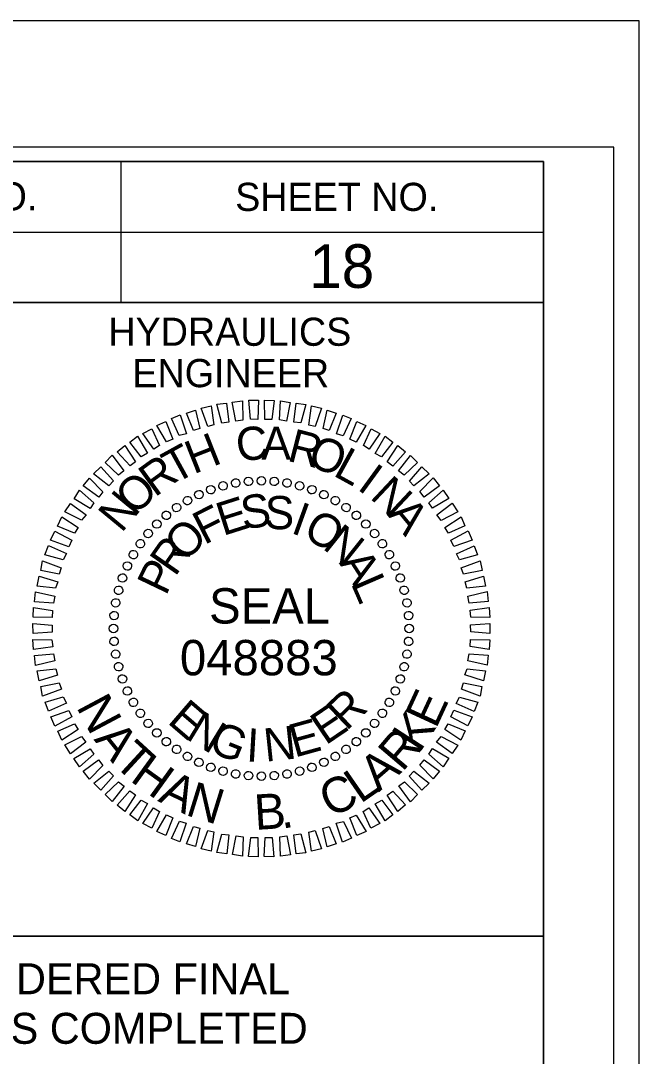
# Model space of a CAD drawing. Extents: x 1648435 to 1651603, y 802691 to 845762.
# Drawn here: x 1650436.5 to 1650546.3, y 803607.1 to 803791 of the extents above; entities that cross this region are included whole.
import ezdxf

# ---------------------------------------------------------------- set-up
doc = ezdxf.new("R2010")
doc.units = 0
for name, color, linetype in [('Default', 7, 'Continuous'), ('Old_Level_2', 7, 'Continuous'), ('Sheet Cutting Line CELL', 7, 'Continuous'), ('Sheet Data Field CELL', 7, 'Continuous'), ('Sheet Plot Border Inside CELL', 7, 'Continuous'), ('Sheet Plot Border Outside CELL', 7, 'Continuous'), ('Sheet Profile CELL', 7, 'Continuous'), ('Sheet Profile Grid Major CELL', 7, 'Continuous'), ('Sheet Sticker Exception Certification CELL', 7, 'Continuous')]:
    doc.layers.add(name, color=color, linetype=linetype)

msp = doc.modelspace()

# ---------------------------------------------------------------- linework, layer by layer
at = {"layer": 'Old_Level_2'}
for p, q in [((1650476.94, 803709.25), (1650476.94, 803709.25)), ((1650479.24, 803709.34), (1650479.24, 803709.34)), ((1650481.55, 803709.22), (1650481.55, 803709.22)), ((1650470.22, 803707.77), (1650470.22, 803707.77)), ((1650472.41, 803708.44), (1650472.41, 803708.44)), ((1650474.7, 803708.89), (1650474.7, 803708.89)), ((1650483.8, 803708.9), (1650483.8, 803708.9)), ((1650486.01, 803708.46), (1650486.01, 803708.46)), ((1650488.21, 803707.77), (1650488.21, 803707.77)), ((1650466.13, 803705.82), (1650466.13, 803705.82)), ((1650468.15, 803706.9), (1650468.15, 803706.9)), ((1650490.32, 803706.87), (1650490.32, 803706.87)), ((1650492.38, 803705.86), (1650492.38, 803705.86)), ((1650464.16, 803704.58), (1650464.16, 803704.58)), ((1650494.28, 803704.58), (1650494.28, 803704.58)), ((1650460.66, 803701.64), (1650460.66, 803701.64)), ((1650462.35, 803703.24), (1650462.35, 803703.24)), ((1650496.14, 803703.2), (1650496.14, 803703.2)), ((1650497.79, 803701.66), (1650497.79, 803701.66)), ((1650459.12, 803699.99), (1650459.12, 803699.99)), ((1650499.38, 803699.96), (1650499.38, 803699.96)), ((1650457.74, 803698.14), (1650457.74, 803698.14)), ((1650500.72, 803698.16), (1650500.72, 803698.16)), ((1650456.46, 803696.23), (1650456.46, 803696.23)), ((1650501.96, 803696.19), (1650501.96, 803696.19)), ((1650455.45, 803694.18), (1650455.45, 803694.18)), ((1650503.04, 803694.17), (1650503.04, 803694.17)), ((1650454.55, 803692.07), (1650454.55, 803692.07)), ((1650503.91, 803692.09), (1650503.91, 803692.09)), ((1650453.85, 803689.86), (1650453.85, 803689.86)), ((1650504.58, 803689.91), (1650504.58, 803689.91)), ((1650453.42, 803687.66), (1650453.42, 803687.66)), ((1650505.04, 803687.62), (1650505.04, 803687.62)), ((1650453.1, 803685.4), (1650453.1, 803685.4)), ((1650505.39, 803685.37), (1650505.39, 803685.37)), ((1650452.98, 803683.1), (1650452.98, 803683.1)), ((1650479.23, 803683.09), (1650479.23, 803683.09)), ((1650505.48, 803683.07), (1650505.48, 803683.07)), ((1650453.07, 803680.8), (1650453.07, 803680.8)), ((1650505.37, 803680.77), (1650505.37, 803680.77)), ((1650453.42, 803678.56), (1650453.42, 803678.56)), ((1650505.04, 803678.52), (1650505.04, 803678.52)), ((1650453.88, 803676.26), (1650453.88, 803676.26)), ((1650504.61, 803676.31), (1650504.61, 803676.31)), ((1650454.55, 803674.08), (1650454.55, 803674.08)), ((1650503.92, 803674.1), (1650503.92, 803674.1)), ((1650455.42, 803672), (1650455.42, 803672)), ((1650503.01, 803672), (1650503.01, 803672)), ((1650456.5, 803669.98), (1650456.5, 803669.98)), ((1650502, 803669.94), (1650502, 803669.94)), ((1650457.74, 803668.02), (1650457.74, 803668.02)), ((1650500.73, 803668.03), (1650500.73, 803668.03)), ((1650459.08, 803666.21), (1650459.08, 803666.21)), ((1650499.35, 803666.18), (1650499.35, 803666.18)), ((1650460.68, 803664.51), (1650460.68, 803664.51)), ((1650497.81, 803664.53), (1650497.81, 803664.53)), ((1650462.32, 803662.97), (1650462.32, 803662.97)), ((1650464.18, 803661.59), (1650464.18, 803661.59)), ((1650494.3, 803661.59), (1650494.3, 803661.59)), ((1650496.11, 803662.93), (1650496.11, 803662.93)), ((1650466.08, 803660.32), (1650466.08, 803660.32)), ((1650468.14, 803659.31), (1650468.14, 803659.31)), ((1650492.34, 803660.36), (1650492.34, 803660.36)), ((1650470.25, 803658.4), (1650470.25, 803658.4)), ((1650472.46, 803657.71), (1650472.46, 803657.71)), ((1650486.05, 803657.74), (1650486.05, 803657.74)), ((1650488.24, 803658.4), (1650488.24, 803658.4)), ((1650490.32, 803659.28), (1650490.32, 803659.28)), ((1650474.66, 803657.28), (1650474.66, 803657.28)), ((1650476.92, 803656.95), (1650476.92, 803656.95)), ((1650479.22, 803656.83), (1650479.22, 803656.83)), ((1650481.52, 803656.93), (1650481.52, 803656.93)), ((1650483.76, 803657.28), (1650483.76, 803657.28))]:
    msp.add_line(p, q, dxfattribs=at)
for points in [[(1650467.22, 803718.23), (1650465.96, 803721.34), (1650467.57, 803721.84), (1650468.31, 803718.61)], [(1650469.71, 803718.95), (1650468.56, 803722.23), (1650470.33, 803722.62), (1650470.81, 803719.23)], [(1650472.21, 803719.57), (1650471.32, 803722.9), (1650473.04, 803723.09), (1650473.47, 803719.75)], [(1650474.72, 803719.93), (1650474.08, 803723.26), (1650475.86, 803723.5), (1650475.97, 803720.11)], [(1650477.33, 803720.24), (1650477.01, 803723.63), (1650478.73, 803723.61), (1650478.58, 803720.21)], [(1650479.84, 803720.23), (1650479.78, 803723.63), (1650481.5, 803723.6), (1650481.09, 803720.2)], [(1650482.45, 803720.12), (1650482.6, 803723.52), (1650484.34, 803723.23), (1650483.71, 803719.93)], [(1650484.97, 803719.74), (1650485.38, 803723.1), (1650487.11, 803722.86), (1650486.23, 803719.61)], [(1650487.65, 803719.21), (1650488.11, 803722.62), (1650489.9, 803722.23), (1650488.75, 803718.97)], [(1650464.67, 803717.35), (1650463.26, 803720.36), (1650464.82, 803721.01), (1650465.97, 803717.68)], [(1650490.17, 803718.58), (1650490.9, 803721.83), (1650492.53, 803721.34), (1650491.27, 803718.23)], [(1650492.54, 803717.68), (1650493.68, 803720.99), (1650495.16, 803720.39), (1650493.75, 803717.33)], [(1650460.16, 803714.92), (1650458.18, 803717.71), (1650459.79, 803718.57), (1650461.15, 803715.56)], [(1650462.39, 803716.21), (1650460.66, 803719.11), (1650462.27, 803719.87), (1650463.53, 803716.7)], [(1650494.91, 803716.72), (1650496.16, 803719.83), (1650497.79, 803719.13), (1650496.07, 803716.17)], [(1650497.33, 803715.56), (1650498.69, 803718.57), (1650500.28, 803717.71), (1650498.34, 803714.95)], [(1650457.89, 803713.57), (1650455.9, 803716.2), (1650457.25, 803717.22), (1650459.02, 803714.22)], [(1650499.4, 803714.19), (1650501.17, 803717.25), (1650502.55, 803716.18), (1650500.56, 803713.58)], [(1650455.93, 803711.97), (1650453.63, 803714.44), (1650455.03, 803715.56), (1650456.91, 803712.66)], [(1650501.57, 803712.66), (1650503.45, 803715.57), (1650504.83, 803714.44), (1650502.57, 803711.94)], [(1650453.86, 803710.31), (1650451.52, 803712.57), (1650452.76, 803713.85), (1650454.84, 803711.06)], [(1650503.58, 803711.07), (1650505.68, 803713.83), (1650506.96, 803712.59), (1650504.59, 803710.3)], [(1650452.17, 803708.45), (1650449.47, 803710.55), (1650450.75, 803711.77), (1650452.99, 803709.3)], [(1650505.5, 803709.27), (1650507.7, 803711.77), (1650508.98, 803710.54), (1650506.3, 803708.45)], [(1650450.37, 803706.43), (1650447.62, 803708.42), (1650448.75, 803709.8), (1650451.09, 803707.38)], [(1650507.36, 803707.42), (1650509.72, 803709.82), (1650510.85, 803708.43), (1650508.11, 803706.39)], [(1650448.84, 803704.42), (1650445.99, 803706.14), (1650446.95, 803707.68), (1650449.5, 803705.42)], [(1650508.96, 803705.41), (1650511.49, 803707.65), (1650512.51, 803706.15), (1650509.61, 803704.43)], [(1650447.31, 803702.3), (1650444.35, 803703.81), (1650445.37, 803705.3), (1650448.13, 803703.25)], [(1650510.36, 803703.29), (1650513.1, 803705.33), (1650514.12, 803703.78), (1650511.11, 803702.26)], [(1650446.09, 803700.03), (1650443.09, 803701.28), (1650443.85, 803702.92), (1650446.7, 803701.03)], [(1650511.76, 803701.02), (1650514.66, 803702.9), (1650515.36, 803701.29), (1650512.41, 803700.03)], [(1650445.09, 803697.6), (1650441.83, 803698.75), (1650442.58, 803700.38), (1650445.59, 803698.76)], [(1650512.85, 803698.79), (1650515.9, 803700.41), (1650516.61, 803698.75), (1650513.39, 803697.65)], [(1650444.08, 803695.29), (1650440.83, 803696.17), (1650441.48, 803697.8), (1650444.64, 803696.39)], [(1650513.83, 803696.35), (1650516.99, 803697.76), (1650517.6, 803696.15), (1650514.37, 803695.26)], [(1650443.34, 803692.76), (1650440.09, 803693.39), (1650440.43, 803695.12), (1650443.74, 803693.87)], [(1650514.71, 803693.85), (1650518.03, 803695.11), (1650518.38, 803693.39), (1650515.09, 803692.76)], [(1650442.71, 803690.24), (1650439.46, 803690.6), (1650439.79, 803692.39), (1650443.11, 803691.35)], [(1650515.38, 803691.35), (1650518.66, 803692.4), (1650519, 803690.63), (1650515.71, 803690.26)], [(1650442.34, 803687.57), (1650438.99, 803687.82), (1650439.16, 803689.6), (1650442.58, 803688.83)], [(1650515.89, 803688.85), (1650519.28, 803689.64), (1650519.47, 803687.87), (1650516.13, 803687.6)], [(1650442.12, 803685.05), (1650438.72, 803685.1), (1650438.79, 803686.83), (1650442.2, 803686.31)], [(1650516.25, 803686.35), (1650519.64, 803686.82), (1650519.78, 803685.05), (1650516.38, 803685.09)], [(1650442.11, 803682.44), (1650438.72, 803682.22), (1650438.69, 803684), (1650442.09, 803683.69)], [(1650516.35, 803683.73), (1650519.75, 803683.95), (1650519.78, 803682.17), (1650516.37, 803682.48)], [(1650442.21, 803679.83), (1650438.82, 803679.35), (1650438.68, 803681.12), (1650442.08, 803681.08)], [(1650516.34, 803681.12), (1650519.74, 803681.07), (1650519.67, 803679.35), (1650516.26, 803679.86)], [(1650442.57, 803677.32), (1650439.18, 803676.53), (1650438.99, 803678.3), (1650442.34, 803678.57)], [(1650516.13, 803678.61), (1650519.48, 803678.35), (1650519.3, 803676.57), (1650515.89, 803677.35)], [(1650443.08, 803674.82), (1650439.81, 803673.77), (1650439.46, 803675.54), (1650442.75, 803675.91)], [(1650515.75, 803675.93), (1650519, 803675.57), (1650518.67, 803673.79), (1650515.36, 803674.83)], [(1650443.75, 803672.32), (1650440.43, 803671.06), (1650440.08, 803672.78), (1650443.37, 803673.41)], [(1650515.12, 803673.41), (1650518.37, 803672.79), (1650518.04, 803671.06), (1650514.72, 803672.31)], [(1650444.63, 803669.83), (1650441.47, 803668.41), (1650440.86, 803670.02), (1650444.09, 803670.92)], [(1650514.38, 803670.89), (1650517.64, 803670), (1650516.98, 803668.37), (1650513.82, 803669.78)], [(1650445.62, 803667.39), (1650442.56, 803665.76), (1650441.85, 803667.42), (1650445.07, 803668.53)], [(1650513.37, 803668.57), (1650516.64, 803667.42), (1650515.88, 803665.79), (1650512.87, 803667.41)], [(1650446.7, 803665.16), (1650443.81, 803663.28), (1650443.1, 803664.88), (1650446.06, 803666.14)], [(1650512.37, 803666.15), (1650515.37, 803664.89), (1650514.62, 803663.26), (1650511.76, 803665.14)], [(1650448.1, 803662.88), (1650445.37, 803660.84), (1650444.34, 803662.4), (1650447.35, 803663.91)], [(1650511.15, 803663.88), (1650514.11, 803662.36), (1650513.09, 803660.88), (1650510.33, 803662.92)], [(1650449.5, 803660.76), (1650446.97, 803658.52), (1650445.96, 803660.02), (1650448.85, 803661.74)], [(1650509.62, 803661.76), (1650512.48, 803660.03), (1650511.51, 803658.5), (1650508.96, 803660.75)], [(1650451.1, 803658.75), (1650448.74, 803656.35), (1650447.62, 803657.75), (1650450.35, 803659.78)], [(1650508.09, 803659.74), (1650510.84, 803657.75), (1650509.72, 803656.37), (1650507.37, 803658.79)], [(1650452.97, 803656.9), (1650450.76, 803654.4), (1650449.48, 803655.63), (1650452.17, 803657.72)], [(1650506.29, 803657.72), (1650509, 803655.63), (1650507.71, 803654.4), (1650505.47, 803656.87)], [(1650454.88, 803655.1), (1650452.78, 803652.35), (1650451.51, 803653.58), (1650453.87, 803655.87)], [(1650504.6, 803655.86), (1650506.94, 803653.6), (1650505.71, 803652.33), (1650503.62, 803655.12)], [(1650456.89, 803653.52), (1650455.01, 803650.61), (1650453.63, 803651.73), (1650455.89, 803654.23)], [(1650502.54, 803654.21), (1650504.83, 803651.74), (1650503.44, 803650.61), (1650501.56, 803653.51)], [(1650459.06, 803651.98), (1650457.29, 803648.92), (1650455.91, 803649.99), (1650457.9, 803652.59)], [(1650500.58, 803652.6), (1650502.56, 803649.97), (1650501.22, 803648.95), (1650499.44, 803651.96)], [(1650461.13, 803650.61), (1650459.77, 803647.6), (1650458.18, 803648.46), (1650460.12, 803651.22)], [(1650498.3, 803651.26), (1650500.28, 803648.47), (1650498.68, 803647.6), (1650497.32, 803650.61)], [(1650463.55, 803649.45), (1650462.3, 803646.34), (1650460.67, 803647.04), (1650462.39, 803650)], [(1650465.92, 803648.5), (1650464.78, 803645.18), (1650463.3, 803645.78), (1650464.72, 803648.84)], [(1650493.79, 803648.82), (1650495.2, 803645.82), (1650493.65, 803645.16), (1650492.49, 803648.49)], [(1650496.07, 803649.96), (1650497.8, 803647.06), (1650496.19, 803646.3), (1650494.93, 803649.47)], [(1650468.29, 803647.6), (1650467.57, 803644.34), (1650465.94, 803644.83), (1650467.19, 803647.94)], [(1650470.81, 803646.96), (1650470.35, 803643.55), (1650468.57, 803643.94), (1650469.71, 803647.2)], [(1650473.49, 803646.43), (1650473.08, 803643.08), (1650471.35, 803643.31), (1650472.23, 803646.57)], [(1650486.25, 803646.6), (1650487.14, 803643.27), (1650485.42, 803643.08), (1650485, 803646.42)], [(1650488.75, 803647.22), (1650489.9, 803643.95), (1650488.13, 803643.55), (1650487.65, 803646.94)], [(1650491.25, 803647.94), (1650492.5, 803644.83), (1650490.89, 803644.33), (1650490.15, 803647.56)], [(1650476.01, 803646.06), (1650475.86, 803642.65), (1650474.13, 803642.94), (1650474.75, 803646.24)], [(1650478.62, 803645.95), (1650478.68, 803642.55), (1650476.96, 803642.57), (1650477.37, 803645.98)], [(1650481.13, 803645.94), (1650481.46, 803642.54), (1650479.73, 803642.57), (1650479.88, 803645.97)], [(1650483.74, 803646.24), (1650484.38, 803642.91), (1650482.6, 803642.67), (1650482.49, 803646.07)]]:
    msp.add_lwpolyline(points, close=True, dxfattribs=at)
for centre, major_axis in [((1650472.44, 803708.42), (-0.195, 0.727)), ((1650474.68, 803708.92), (-0.131, 0.742)), ((1650476.95, 803709.21), (-0.066, 0.75)), ((1650479.23, 803709.31), (0, 0.753)), ((1650481.52, 803709.21), (0.066, 0.75)), ((1650483.79, 803708.92), (0.131, 0.742)), ((1650486.02, 803708.42), (0.195, 0.727)), ((1650468.15, 803706.86), (-0.318, 0.682)), ((1650470.26, 803707.73), (-0.258, 0.708)), ((1650488.2, 803707.73), (0.258, 0.708)), ((1650490.32, 803706.86), (0.318, 0.682)), ((1650464.19, 803704.57), (-0.432, 0.617)), ((1650466.12, 803705.8), (-0.376, 0.652)), ((1650492.35, 803705.8), (0.376, 0.652)), ((1650494.27, 803704.57), (0.432, 0.617)), ((1650462.37, 803703.18), (-0.484, 0.577)), ((1650496.09, 803703.18), (0.484, 0.577)), ((1650460.69, 803701.63), (-0.532, 0.532)), ((1650497.78, 803701.63), (0.532, 0.532)), ((1650459.14, 803699.95), (-0.577, 0.484)), ((1650499.32, 803699.95), (0.577, 0.484)), ((1650457.75, 803698.13), (-0.617, 0.432)), ((1650500.72, 803698.13), (0.617, 0.432)), ((1650456.52, 803696.2), (-0.652, 0.376)), ((1650501.95, 803696.2), (0.652, 0.376)), ((1650455.46, 803694.17), (-0.682, 0.318)), ((1650503, 803694.17), (0.682, 0.318)), ((1650454.59, 803692.06), (-0.708, 0.258)), ((1650503.88, 803692.06), (0.708, 0.258)), ((1650453.9, 803689.87), (-0.727, 0.195)), ((1650504.57, 803689.87), (0.727, 0.195)), ((1650453.4, 803687.64), (-0.742, 0.131)), ((1650505.06, 803687.64), (0.742, 0.131)), ((1650453.1, 803685.37), (-0.75, 0.066)), ((1650505.36, 803685.37), (0.75, 0.066)), ((1650453, 803683.09), (-0.753, 0)), ((1650505.46, 803683.09), (0.753, 0)), ((1650453.1, 803680.8), (-0.75, -0.066)), ((1650505.36, 803680.8), (0.75, -0.066)), ((1650453.4, 803678.53), (-0.742, -0.131)), ((1650505.06, 803678.53), (0.742, -0.131)), ((1650453.9, 803676.3), (-0.727, -0.195)), ((1650504.57, 803676.3), (0.727, -0.195)), ((1650454.59, 803674.12), (-0.708, -0.258)), ((1650503.88, 803674.12), (0.708, -0.258)), ((1650455.46, 803672), (-0.682, -0.318)), ((1650503, 803672), (0.682, -0.318)), ((1650456.52, 803669.97), (-0.652, -0.376)), ((1650501.95, 803669.97), (0.652, -0.376)), ((1650457.75, 803668.04), (-0.617, -0.432)), ((1650500.72, 803668.04), (0.617, -0.432)), ((1650459.14, 803666.23), (-0.577, -0.484)), ((1650499.32, 803666.23), (0.577, -0.484)), ((1650460.69, 803664.54), (-0.532, -0.532)), ((1650497.78, 803664.54), (0.532, -0.532)), ((1650462.37, 803662.99), (-0.484, -0.577)), ((1650496.09, 803662.99), (0.484, -0.577)), ((1650464.19, 803661.6), (-0.432, -0.617)), ((1650466.12, 803660.37), (-0.376, -0.652)), ((1650492.35, 803660.37), (0.376, -0.652)), ((1650494.27, 803661.6), (0.432, -0.617)), ((1650468.15, 803659.32), (-0.318, -0.682)), ((1650490.32, 803659.32), (0.318, -0.682)), ((1650470.26, 803658.44), (-0.258, -0.708)), ((1650472.44, 803657.75), (-0.195, -0.727)), ((1650474.68, 803657.26), (-0.131, -0.742)), ((1650476.95, 803656.96), (-0.066, -0.75)), ((1650479.23, 803656.86), (0, -0.753)), ((1650481.52, 803656.96), (0.066, -0.75)), ((1650483.79, 803657.26), (0.131, -0.742)), ((1650486.02, 803657.75), (0.195, -0.727)), ((1650488.2, 803658.44), (0.258, -0.708))]:
    msp.add_ellipse(centre, major_axis=major_axis, ratio=0.999708, dxfattribs=at)
at = {"layer": 'Sheet Cutting Line CELL'}
msp.add_line((1650546.28, 803791.02), (1648862.28, 803791.02), dxfattribs=at)
at = {"layer": 'Sheet Plot Border Inside CELL'}
msp.add_lwpolyline([(1648875.28, 802713.47), (1650541.78, 802713.47), (1650541.78, 803768.57), (1648875.28, 803768.57)], close=True, dxfattribs=at)
at = {"layer": 'Sheet Plot Border Outside CELL'}
msp.add_lwpolyline([(1648862.28, 802691.02), (1650546.28, 802691.02), (1650546.28, 803791.02), (1648862.28, 803791.02)], close=True, dxfattribs=at)
at = {"layer": 'Sheet Profile CELL'}
for p, q in [((1650454.28, 803765.97), (1650454.28, 803740.97)), ((1650329.23, 803753.47), (1650529.28, 803753.47))]:
    msp.add_line(p, q, dxfattribs=at)
for points in [[(1650529.28, 803766.02), (1649029.28, 803766.02), (1649029.28, 802716.02), (1650529.28, 802716.02)], [(1650329.23, 803766.02), (1650529.28, 803766.02), (1650529.28, 803740.97), (1650329.23, 803740.97)], [(1650429.28, 803740.97), (1650529.28, 803740.97), (1650529.28, 803628.47), (1650429.28, 803628.47)]]:
    msp.add_lwpolyline(points, close=True, dxfattribs=at)
at = {"layer": 'Sheet Profile Grid Major CELL'}
msp.add_lwpolyline([(1650479.28, 803604.97), (1650479.28, 803266.02), (1650529.28, 803266.02), (1650529.28, 803616.02)], dxfattribs=at)
at = {"layer": 'Sheet Sticker Exception Certification CELL'}
for p, q in [((1650329.23, 803628.47), (1650529.27, 803628.47)), ((1650329.23, 803628.47), (1650529.27, 803628.47)), ((1650529.27, 803628.46), (1650529.27, 803604.96)), ((1650529.27, 803628.46), (1650529.27, 803604.96))]:
    msp.add_line(p, q, dxfattribs=at)

# ---------------------------------------------------------------- texts
at = {"layer": 'Default'}
for s, rotation, p in [('E', 65.2198, (1650510.2, 803665.13)), ('N', 298.0773, (1650446.31, 803669.19)), ('K', 57.024, (1650507.33, 803660.9)), ('A', 308.6891, (1650449.42, 803663.36)), ('R', 49.6233, (1650504.25, 803657.47)), ('T', 317.4354, (1650452.76, 803659.05)), ('H', 324.1633, (1650455.75, 803656.11)), ('A', 40.877, (1650500.07, 803653.97)), ('L', 34.6689, (1650496.8, 803651.89)), ('A', 334.0411, (1650460.72, 803652.48)), ('N', 342.7874, (1650465.58, 803650.01)), ('C', 25.1886, (1650491.43, 803649.42)), ('B', 3.4911, (1650478.14, 803647.31)), ('.', 11.1059, (1650482.89, 803647.47))]:
    msp.add_text(s, height=6.27, rotation=rotation, dxfattribs=at).set_placement(p)
at = {"layer": 'Old_Level_2'}
for s, rotation, p in [('C', 7.2199, (1650475.11, 803712.67)), ('A', 0.0203, (1650479.23, 803713.05)), ('R', 345.6211, (1650483.63, 803712.92)), ('H', 21.6195, (1650467.2, 803710.44)), ('O', 338.4212, (1650487.14, 803712.2)), ('T', 28.8198, (1650463.83, 803708.65)), ('L', 331.2209, (1650491.78, 803710.34)), ('R', 36.0205, (1650460.31, 803706.29)), ('I', 324.0201, (1650496.06, 803707.91)), ('O', 43.2217, (1650456.76, 803702.99)), ('N', 316.8189, (1650498.33, 803706.33)), ('N', 50.4235, (1650454.41, 803699.91)), ('E', 17.6111, (1650472.41, 803699.49)), ('S', 8.2556, (1650476, 803700.65)), ('S', 358.9004, (1650479.76, 803700.77)), ('I', 340.1896, (1650484.27, 803700.12)), ('A', 309.6172, (1650501.47, 803703.29)), ('F', 26.967, (1650469.09, 803697.87)), ('O', 330.8335, (1650486.37, 803699.42)), ('O', 45.6812, (1650465.69, 803694.72)), ('N', 321.4766, (1650489.91, 803697.39)), ('R', 55.0397, (1650463.91, 803692.13)), ('P', 64.3989, (1650462.29, 803688.75)), ('A', 302.7603, (1650492.94, 803694.73)), ('L', 293.4009, (1650495.04, 803691.15)), ('E', 319.2769, (1650462.37, 803666.42)), ('R', 43.4814, (1650494.3, 803664.78)), ('E', 34.1241, (1650490.63, 803662.26)), ('N', 328.634, (1650465.56, 803663.65)), ('E', 15.4118, (1650485.12, 803660.13)), ('G', 337.9902, (1650469.57, 803661.37)), ('I', 356.7012, (1650476.45, 803659.5)), ('N', 6.0564, (1650479.96, 803659.41))]:
    msp.add_text(s, height=5.9, rotation=rotation, dxfattribs=at).set_placement(p)
for s, height, p in [('SEAL', 6.273, (1650469.96, 803683.97)), ('048883', 6.275, (1650464.78, 803674.77))]:
    msp.add_text(s, height=height, dxfattribs=at).set_placement(p)
at = {"layer": 'Sheet Data Field CELL'}
msp.add_text('18', height=7.75, dxfattribs=at).set_placement((1650487.73, 803743.57))
at = {"layer": 'Sheet Profile CELL'}
for s, height, p in [('PROJECT REFERENCE NO.', 5.0001, (1650351.44, 803757.34)), ('SHEET NO.', 5, (1650474.59, 803757.24)), ('HYDRAULICS', 5, (1650452.09, 803733.29)), ('ENGINEER', 5, (1650456.34, 803725.94))]:
    msp.add_text(s, height=height, dxfattribs=at).set_placement(p)
at = {"layer": 'Sheet Sticker Exception Certification CELL'}
for s, p in [('DOCUMENT NOT CONSIDERED FINAL', (1650350.3, 803618.13)), ('DOCUMENT NOT CONSIDERED FINAL', (1650350.3, 803618.13)), ('UNLESS ALL SIGNATURES COMPLETED', (1650345.23, 803609.33)), ('UNLESS ALL SIGNATURES COMPLETED', (1650345.23, 803609.33))]:
    msp.add_text(s, height=5.5, dxfattribs=at).set_placement(p)

doc.saveas('drawing.dxf')
